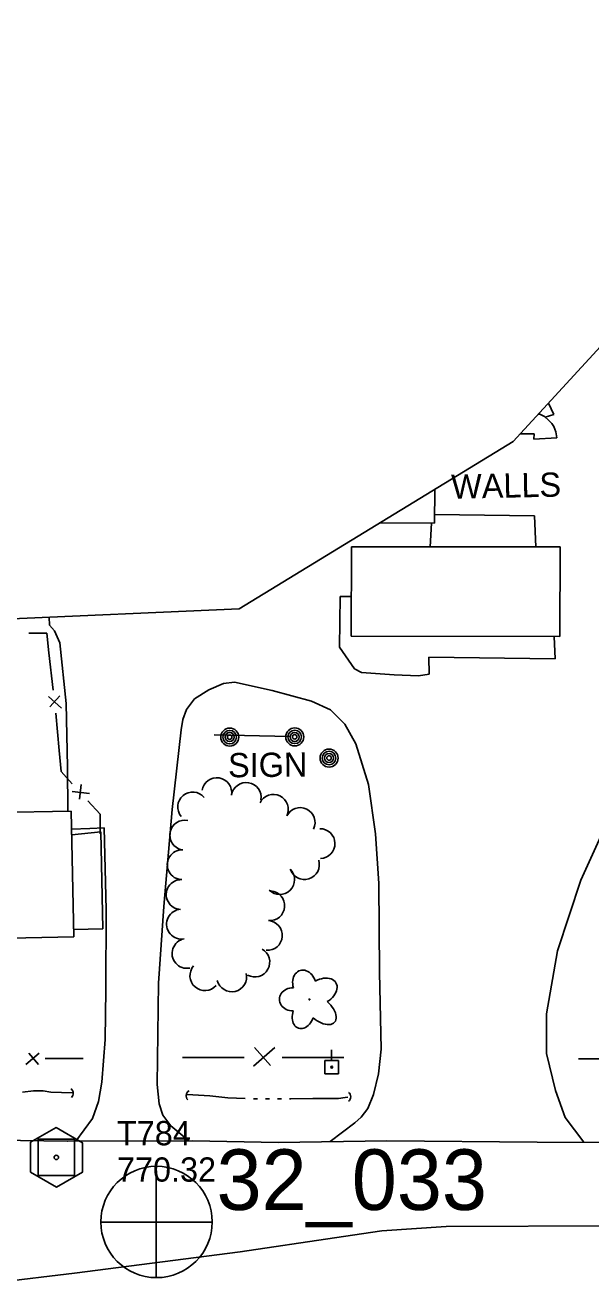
# Model space of a CAD drawing. Extents: x 589250 to 1188077, y 162953 to 363065.
# Drawn here: x 592836.3 to 592976.3, y 175676.4 to 175987.9 of the extents above; entities that cross this region are included whole.
import ezdxf

# ---------------------------------------------------------------- set-up
doc = ezdxf.new("R2010")
doc.units = 0
for name, color, linetype in [('E_BLD', 7, 'Continuous'), ('E_BLD_HvyDash', 7, 'Continuous'), ('E_DRN', 7, 'Continuous'), ('E_DWY', 7, 'Continuous'), ('E_FEN_P', 7, 'Continuous'), ('E_LAND_TreeLine_P', 7, 'Continuous'), ('E_LAND_Vegetation', 7, 'Continuous'), ('E_MAP_Control', 7, 'Continuous'), ('E_MAP_Limits', 7, 'Continuous'), ('E_MAP_PhotoCenter', 7, 'Continuous'), ('E_MISCPROP', 7, 'Continuous'), ('E_PATH_Sidewalk', 7, 'Continuous'), ('E_RDWY', 7, 'Continuous'), ('E_SGN', 7, 'Continuous'), ('E_SGN_Text', 7, 'Continuous'), ('E_UTL_EPowerPole', 7, 'Continuous'), ('E_WAL', 7, 'Continuous'), ('E_WAL_Text', 7, 'Continuous'), ('E_WTR_FlowLine', 7, 'Continuous')]:
    doc.layers.add(name, color=color, linetype=linetype)

msp = doc.modelspace()

# ---------------------------------------------------------------- linework, layer by layer
at = {"layer": 'E_BLD'}
for p, q in [((592937.66, 175873.01), (592937.62, 175864.65)), ((592937.62, 175864.65), (592924.05, 175864.71)), ((592917.03, 175858.81), (592917.02, 175836.65)), ((592968.68, 175858.78), (592917.03, 175858.81)), ((592968.67, 175836.61), (592968.68, 175858.78)), ((592917.02, 175836.65), (592968.67, 175836.61)), ((592817.23, 175792.75), (592847.69, 175793.38)), ((592847.69, 175793.38), (592848.33, 175762.27)), ((592848.33, 175762.27), (592832.5, 175761.94))]:
    msp.add_line(p, q, dxfattribs=at)
at = {"layer": 'E_BLD_HvyDash'}
for p, q in [((592847.81, 175787.51), (592855.05, 175788.23)), ((592855.05, 175788.23), (592855.55, 175764.25)), ((592855.55, 175764.25), (592848.29, 175764.1))]:
    msp.add_line(p, q, dxfattribs=at)
at = {"layer": 'E_DRN'}
for centre, radius, start, end in [((592846.85, 175723.5), 1.37, 311.2363, 57.4965), ((592877.53, 175722.89), 1.39, 118.5941, 224.8543), ((592915.51, 175722.62), 1.38, 308.0565, 54.3167)]:
    msp.add_arc(centre, radius, start, end, dxfattribs=at)
at = {"layer": 'E_DWY'}
for p, q in [((592967.18, 175891.59), (592965.83, 175894.38)), ((592965.01, 175890.9), (592967.18, 175891.59)), ((592962.4, 175866.44), (592962.7, 175858.79)), ((592842.23, 175841.4), (592842.28, 175839.38)), ((592842.28, 175839.38), (592843.53, 175838)), ((592843.53, 175838), (592844.87, 175834.99)), ((592844.87, 175834.99), (592846.45, 175820)), ((592878.2, 175821.19), (592881.78, 175823.4)), ((592881.78, 175823.4), (592885.38, 175824.96)), ((592885.38, 175824.96), (592888.08, 175825.31)), ((592888.08, 175825.31), (592897.44, 175823.22)), ((592897.44, 175823.22), (592907.17, 175820.58)), ((592876.19, 175818.51), (592878.2, 175821.19)), ((592907.17, 175820.58), (592911.91, 175818.47)), ((592846.45, 175820), (592846.78, 175804.37)), ((592875.32, 175816.07), (592876.19, 175818.51)), ((592911.91, 175818.47), (592915.4, 175814.91)), ((592874.94, 175813.5), (592875.32, 175816.07)), ((592915.4, 175814.91), (592918.14, 175809.99)), ((592872.65, 175793.75), (592874.94, 175813.5)), ((592973.82, 175776.26), (592989.65, 175811.13)), ((592918.14, 175809.99), (592921.26, 175799.95)), ((592846.78, 175804.37), (592846.88, 175793.36)), ((592921.26, 175799.95), (592923.01, 175787.74)), ((592870.65, 175769.79), (592872.65, 175793.75)), ((592852.31, 175789.03), (592847.78, 175788.94)), ((592855.83, 175789.23), (592852.31, 175789.03)), ((592856.37, 175768.92), (592855.83, 175789.23)), ((592923.01, 175787.74), (592923.84, 175775.45)), ((592923.84, 175775.45), (592924, 175753.54)), ((592968.06, 175758.77), (592973.82, 175776.26)), ((592856.24, 175749.09), (592856.37, 175768.92)), ((592869.27, 175750.76), (592870.65, 175769.79)), ((592965.31, 175743.19), (592968.06, 175758.77)), ((592924, 175753.54), (592924.4, 175734.47)), ((592856.13, 175736.86), (592856.24, 175749.09)), ((592868.93, 175725.71), (592869.27, 175750.76)), ((592965.31, 175733.38), (592965.31, 175743.19)), ((592855.25, 175726.25), (592856.13, 175736.86)), ((592924.4, 175734.47), (592923.74, 175728.34)), ((592967.54, 175724.23), (592965.31, 175733.38)), ((592923.74, 175728.34), (592922.5, 175723.26)), ((592854.44, 175721.49), (592855.25, 175726.25)), ((592869.46, 175720.95), (592868.93, 175725.71)), ((592969.93, 175717.54), (592967.54, 175724.23)), ((592853, 175717.26), (592854.44, 175721.49)), ((592870.37, 175718.12), (592869.46, 175720.95)), ((592922.5, 175723.26), (592921.08, 175719.74)), ((592848.8, 175711.7), (592853, 175717.26)), ((592872.35, 175715.46), (592870.37, 175718.12)), ((592919.48, 175717.58), (592917.88, 175716.19)), ((592921.08, 175719.74), (592919.48, 175717.58)), ((592974.55, 175711.39), (592969.93, 175717.54)), ((592876.77, 175711.77), (592872.35, 175715.46)), ((592917.88, 175716.19), (592911.78, 175711.57))]:
    msp.add_line(p, q, dxfattribs=at)
at = {"layer": 'E_FEN_P'}
for p, q in [((592837.21, 175837.41), (592841.62, 175837.46)), ((592841.62, 175837.46), (592842.17, 175832.59)), ((592842.17, 175832.59), (592843.22, 175823.35)), ((592842.09, 175821.78), (592845.26, 175818.88)), ((592844.91, 175821.95), (592842.44, 175819.21)), ((592843.85, 175817.62), (592844.73, 175808.36)), ((592844.73, 175808.36), (592845.22, 175803.16)), ((592845.22, 175803.16), (592847.97, 175800.14)), ((592850.15, 175799.99), (592849.75, 175796.33)), ((592847.96, 175798.2), (592852.23, 175797.7)), ((592851.84, 175795.88), (592854.84, 175792.58)), ((592854.84, 175792.58), (592854.89, 175787.73)), ((592839.78, 175733.49), (592836.5, 175730.66)), ((592839.62, 175730.65), (592837.17, 175733.45)), ((592892.83, 175730.26), (592898.13, 175734.89)), ((592893.06, 175734.88), (592897.06, 175730.36)), ((592850.62, 175732.12), (592841.22, 175732.17)), ((592875.24, 175732.38), (592890.48, 175732.39)), ((592899.91, 175732.4), (592915.15, 175732.42)), ((592973.24, 175732.04), (592985.73, 175732.1))]:
    msp.add_line(p, q, dxfattribs=at)
at = {"layer": 'E_LAND_TreeLine_P'}
for centre, start, end in [((592883.74, 175797.94), 350.7491, 170.7491), ((592891.02, 175796.76), 350.7491, 170.7491), ((592877.75, 175794.4), 39.8464, 219.8464), ((592897.74, 175793.81), 333.8627, 153.8627), ((592904.36, 175790.56), 333.8627, 153.8627), ((592875.79, 175787.43), 77.5596, 257.5596), ((592909.29, 175785.33), 271.1866, 91.1866), ((592875.16, 175780.1), 88.0067, 268.0067), ((592905.43, 175780.14), 197.4468, 17.4468), ((592874.91, 175772.73), 88.0067, 268.0067), ((592899.3, 175776.42), 224.6384, 44.6384), ((592896.83, 175769.95), 265.476, 85.476), ((592874.99, 175765.39), 100.6489, 280.6489), ((592896.25, 175762.59), 265.476, 85.476), ((592876.35, 175758.14), 100.6489, 280.6489), ((592893.14, 175756), 241.0452, 61.0452), ((592880.77, 175752.64), 138.9129, 318.9129), ((592887.43, 175752.34), 193.7154, 13.7154)]:
    msp.add_arc(centre, 3.69, start, end, dxfattribs=at)
at = {"layer": 'E_LAND_Vegetation'}
msp.add_circle((592906.65, 175746.76), 0.128, dxfattribs=at)
for centre, major_axis, ratio in [((592905.4, 175750.46), (1.02, -3.47), 0.782863), ((592909.58, 175748.74), (-3.65, -2.13), 0.691916), ((592902.67, 175746.78), (3.45, -0.01), 0.832022), ((592909.32, 175744.22), (-3.57, 3.13), 0.560249), ((592905.11, 175743.06), (1.19, 3.42), 0.716896)]:
    msp.add_ellipse(centre, major_axis=major_axis, ratio=ratio, start_param=1.570796, end_param=4.712389, dxfattribs=at)
at = {"layer": 'E_MAP_Control'}
for p, q in [((592839.51, 175703.15), (592839.51, 175712.15)), ((592839.51, 175712.15), (592848.51, 175712.15)), ((592839.51, 175703.15), (592839.51, 175712.15)), ((592839.51, 175712.15), (592848.51, 175712.15)), ((592848.51, 175712.15), (592848.51, 175703.15)), ((592848.51, 175712.15), (592848.51, 175703.15)), ((592848.51, 175703.15), (592839.51, 175703.15)), ((592848.51, 175703.15), (592839.51, 175703.15))]:
    msp.add_line(p, q, dxfattribs=at)
msp.add_lwpolyline([(592837.59, 175711.41), (592837.59, 175704.02), (592844.05, 175700.29), (592850.45, 175703.96), (592850.45, 175711.29), (592843.93, 175715.01)], close=True, dxfattribs=at)
msp.add_lwpolyline([(592837.59, 175711.41), (592837.59, 175704.02), (592844.05, 175700.29), (592850.45, 175703.96), (592850.45, 175711.29), (592843.93, 175715.01)], close=True, dxfattribs=at)
msp.add_circle((592844.01, 175707.65), 0.546, dxfattribs=at)
msp.add_circle((592844.01, 175707.65), 0.546, dxfattribs=at)
at = {"layer": 'E_MAP_Limits'}
for p, q in [((593051.75, 175987.93), (592957.08, 175884.85)), ((592957.08, 175884.85), (592889.25, 175843.48)), ((592889.25, 175843.48), (592823.06, 175840.55))]:
    msp.add_line(p, q, dxfattribs=at)
at = {"layer": 'E_MAP_PhotoCenter'}
for p, q in [((592868.76, 175705.46), (592868.7, 175678.05)), ((592868.76, 175705.46), (592868.7, 175678.05)), ((592855.07, 175691.65), (592882.53, 175691.64)), ((592855.07, 175691.65), (592882.53, 175691.64))]:
    msp.add_line(p, q, dxfattribs=at)
msp.add_circle((592868.81, 175691.66), 13.78, dxfattribs=at)
msp.add_circle((592868.81, 175691.66), 13.78, dxfattribs=at)
at = {"layer": 'E_MISCPROP'}
for centre, radius in [((592886.93, 175811.69), 2.23), ((592903.02, 175811.74), 2.23), ((592886.93, 175811.69), 1.67), ((592886.93, 175811.69), 1.12), ((592886.93, 175811.69), 0.558), ((592903.02, 175811.74), 1.67), ((592903.02, 175811.74), 1.12), ((592903.02, 175811.74), 0.558), ((592911.52, 175806.51), 2.23), ((592911.52, 175806.51), 1.67), ((592911.52, 175806.51), 1.12), ((592911.52, 175806.51), 0.558)]:
    msp.add_circle(centre, radius, dxfattribs=at)
at = {"layer": 'E_PATH_Sidewalk'}
for p, q in [((592914.24, 175846.48), (592914.13, 175833.96)), ((592917.02, 175846.53), (592914.24, 175846.48)), ((592967.47, 175831.1), (592967.24, 175836.61)), ((592914.13, 175833.96), (592917.81, 175828.57)), ((592936.2, 175831.5), (592967.47, 175831.1)), ((592936.29, 175827.26), (592936.2, 175831.5)), ((592917.81, 175828.57), (592919.53, 175827.67)), ((592919.53, 175827.67), (592927.63, 175827.08)), ((592927.63, 175827.08), (592933.66, 175826.83)), ((592933.66, 175826.83), (592936.29, 175827.26))]:
    msp.add_line(p, q, dxfattribs=at)
at = {"layer": 'E_RDWY'}
for p, q in [((592846.79, 175711.69), (592827.18, 175711.94)), ((592877.78, 175711.78), (592846.7, 175711.69)), ((592898.93, 175711.37), (592877.78, 175711.78)), ((592925.81, 175711.79), (592898.93, 175711.37)), ((592963.06, 175711.44), (592925.81, 175711.79)), ((593001.86, 175711.27), (592963.06, 175711.44)), ((592912.87, 175687.72), (592924.59, 175689.5)), ((592924.59, 175689.5), (592940.53, 175690.53)), ((592940.53, 175690.53), (592981.14, 175690.67)), ((592889.55, 175684.29), (592912.87, 175687.72)), ((592848.49, 175678.96), (592889.55, 175684.29)), ((592848.49, 175678.96), (592826.76, 175676.35))]:
    msp.add_line(p, q, dxfattribs=at)
at = {"layer": 'E_SGN'}
msp.add_line((592883.08, 175812.22), (592901.83, 175811.83), dxfattribs=at)
at = {"layer": 'E_UTL_EPowerPole'}
for points in [[(592912.15, 175731.66), (592912.15, 175734.31)], [(592913.82, 175731.66), (592910.47, 175731.66)], [(592910.47, 175731.66), (592910.47, 175728.31)], [(592913.82, 175728.31), (592913.82, 175731.66)], [(592910.47, 175728.31), (592913.82, 175728.31)]]:
    msp.add_lwpolyline(points, dxfattribs=at)
msp.add_circle((592912.18, 175729.99), 0.217, dxfattribs=at)
at = {"layer": 'E_WAL'}
for p, q in [((592963.32, 175891.64), (592963.66, 175891.61)), ((592963.66, 175891.61), (592964.84, 175891.04)), ((592964.84, 175891.04), (592965.82, 175890.18)), ((592965.82, 175890.18), (592966.64, 175889.32)), ((592966.64, 175889.32), (592967.17, 175888.59)), ((592967.17, 175888.59), (592967.64, 175887.28)), ((592958.88, 175886.81), (592961.83, 175886.77)), ((592962.29, 175886.8), (592961.83, 175886.77)), ((592962.24, 175885.48), (592962.29, 175886.8)), ((592967.89, 175885.74), (592962.24, 175885.48)), ((592967.64, 175887.28), (592967.89, 175885.74)), ((592937.63, 175866.8), (592962.4, 175866.44)), ((592936.91, 175864.65), (592936.56, 175858.8))]:
    msp.add_line(p, q, dxfattribs=at)
at = {"layer": 'E_WTR_FlowLine'}
for p, q in [((592835.63, 175723.76), (592838.38, 175724.11)), ((592838.38, 175724.11), (592840.76, 175724.13)), ((592840.76, 175724.13), (592842.69, 175723.77)), ((592842.69, 175723.77), (592845.32, 175723.73)), ((592845.32, 175723.73), (592848.21, 175723.63)), ((592876.41, 175723.24), (592882.01, 175722.93)), ((592882.01, 175722.93), (592886.46, 175722.42)), ((592886.46, 175722.42), (592890.79, 175722.2)), ((592892.78, 175722.12), (592893.77, 175722.12)), ((592895.77, 175722.12), (592896.76, 175722.12)), ((592898.75, 175722.13), (592899.75, 175722.13)), ((592901.74, 175722.13), (592902.04, 175722.13)), ((592902.04, 175722.13), (592907.51, 175722.24)), ((592907.51, 175722.24), (592911.46, 175722.27)), ((592911.46, 175722.27), (592913.84, 175722.19)), ((592913.84, 175722.19), (592915.48, 175722.47)), ((592915.48, 175722.47), (592916.14, 175722.54))]:
    msp.add_line(p, q, dxfattribs=at)

# ---------------------------------------------------------------- texts
at = {"layer": 'E_MAP_Control'}
for s, p in [('T784', (592859.01, 175710.65)), ('T784', (592859.01, 175710.65)), ('770.32', (592859.01, 175701.65)), ('770.32', (592859.01, 175701.65))]:
    msp.add_text(s, height=6, dxfattribs=at).set_placement(p)
at = {"layer": 'E_MAP_PhotoCenter'}
msp.add_text('32_033', height=15, dxfattribs=at).set_placement((592883.67, 175694.64))
msp.add_text('32_033', height=15, dxfattribs=at).set_placement((592883.67, 175694.64))
at = {"layer": 'E_SGN_Text'}
msp.add_text('SIGN', height=6, rotation=0.5854, dxfattribs=at).set_placement((592886.55, 175801.73))
at = {"layer": 'E_WAL_Text'}
msp.add_text('WALLS', height=6, rotation=1.1866, dxfattribs=at).set_placement((592941.8, 175870.68))

doc.saveas('drawing.dxf')
